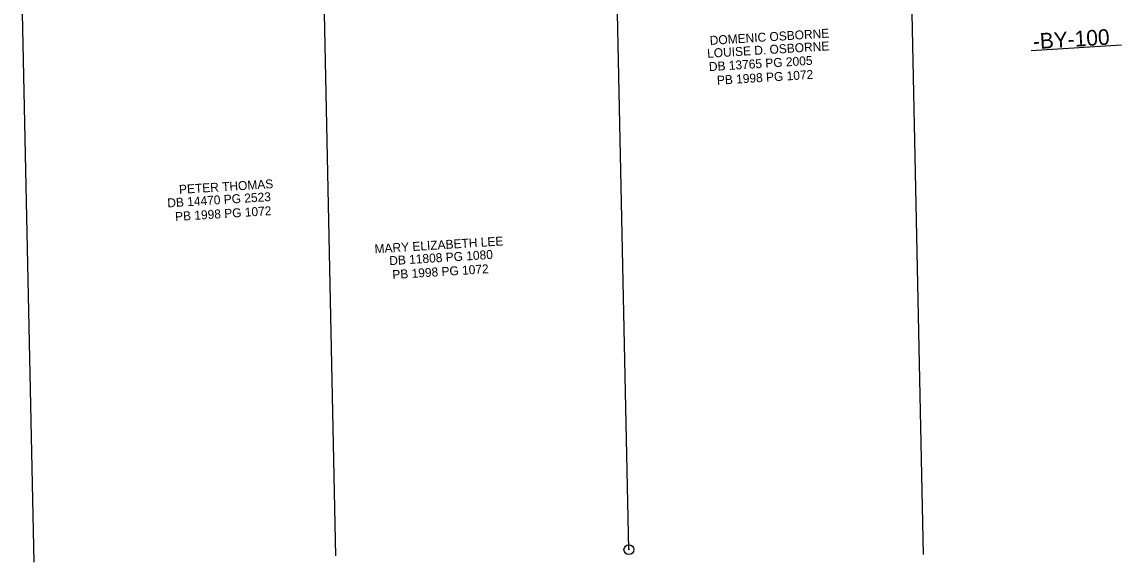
# Model space of a CAD drawing. Extents: x 2110969 to 2113691, y 670003 to 672285.
# Drawn here: x 2111640.2 to 2112129.5, y 670134.1 to 670375.7 of the extents above; entities that cross this region are included whole.
import ezdxf

# ---------------------------------------------------------------- set-up
doc = ezdxf.new("R2010")
doc.units = 0
for name, color, linetype in [('Exist Horizontal Baseline Alignment Station Label', 7, 'Continuous'), ('Exist Property Deed Book Text', 7, 'Continuous'), ('Exist Property Iron Pin CELL', 7, 'Continuous'), ('Exist Property Line', 7, 'Continuous'), ('Exist Property Owner Text', 7, 'Continuous')]:
    doc.layers.add(name, color=color, linetype=linetype)

msp = doc.modelspace()

# ---------------------------------------------------------------- linework, layer by layer
at = {"layer": 'Exist Horizontal Baseline Alignment Station Label'}
msp.add_line((2112131.89, 670365.28), (2112091.49, 670362.84), dxfattribs=at)
at = {"layer": 'Exist Property Iron Pin CELL'}
for radius in [2.2, 0.0707]:
    msp.add_circle((2111911.61, 670139.69), radius, dxfattribs=at)
at = {"layer": 'Exist Property Line'}
for p, q in [((2112043.4, 670137.55), (2112037.49, 670418.75)), ((2111911.61, 670139.69), (2111905.91, 670410.77)), ((2111780.63, 670136.93), (2111775.04, 670402.84)), ((2111645.66, 670134.1), (2111640.18, 670394.67))]:
    msp.add_line(p, q, dxfattribs=at)

# ---------------------------------------------------------------- texts
at = {"layer": 'Exist Horizontal Baseline Alignment Station Label'}
msp.add_text('-BY-100', height=7, rotation=3.4682, dxfattribs=at).set_placement((2112092.45, 670363.52))
at = {"layer": 'Exist Property Deed Book Text'}
for s, p in [('DB 13765 PG 2005', (2111947.5, 670353.69)), ('PB 1998 PG 1072', (2111951.08, 670347.62)), ('DB 14470 PG 2523', (2111705.33, 670292.74)), ('PB 1998 PG 1072', (2111708.82, 670286.66)), ('DB 11808 PG 1080', (2111804.58, 670266.9)), ('PB 1998 PG 1072', (2111805.96, 670260.69))]:
    msp.add_text(s, height=4, rotation=3.5509, dxfattribs=at).set_placement(p)
at = {"layer": 'Exist Property Owner Text'}
for s, p in [('DOMENIC OSBORNE', (2111947.89, 670365.43)), ('LOUISE D. OSBORNE', (2111946.72, 670359.65)), ('PETER THOMAS', (2111710.56, 670298.78)), ('MARY ELIZABETH LEE', (2111798, 670272.2))]:
    msp.add_text(s, height=4, rotation=3.5509, dxfattribs=at).set_placement(p)

doc.saveas('drawing.dxf')
